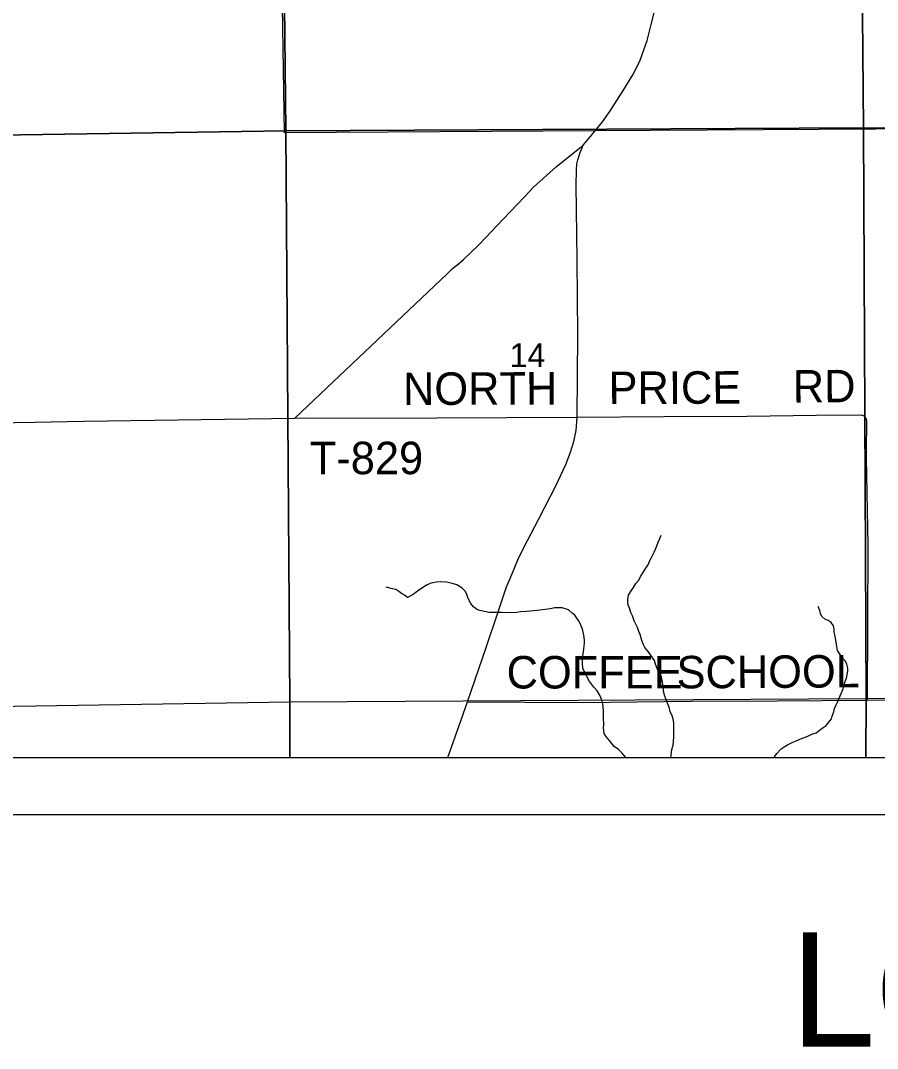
# Model space of a CAD drawing. Extents: x 0 to 34, y 0 to 22.
# Drawn here: x 3.079 to 4.579, y 13.591 to 15.389 of the extents above; entities that cross this region are included whole.
import ezdxf

# ---------------------------------------------------------------- set-up
doc = ezdxf.new("R2010")
doc.units = 0
for name, color, linetype in [('Default', 7, 'Continuous'), ('GM_X_Minor_River', 7, 'Continuous'), ('GM_X_Rail_Line', 7, 'Continuous'), ('GM_X_Section', 7, 'Continuous'), ('GM_X_Section_Text', 7, 'Continuous'), ('GM_X_State_Route', 7, 'Continuous'), ('GM_X_Township', 7, 'Continuous'), ('GM_X_Township_Road', 7, 'Continuous'), ('GM_X_Township_Road_Text', 7, 'Continuous'), ('SH_Cut_Line', 7, 'Continuous'), ('SH_Data', 7, 'Continuous'), ('SH_Text', 7, 'Continuous')]:
    doc.layers.add(name, color=color, linetype=linetype)

msp = doc.modelspace()

# ---------------------------------------------------------------- linework, layer by layer
at = {"layer": 'Default'}
for points in [[(2.5497, 14.1), (3.5508, 14.1), (3.5507, 14.1966), (2.5493, 14.1808)], [(3.5508, 14.1), (4.5592, 14.1), (4.5597, 14.2026), (3.5507, 14.1966)], [(4.5592, 14.1), (5.5573, 14.1), (5.5568, 14.2045), (4.5597, 14.2026)]]:
    msp.add_lwpolyline(points, close=True, dxfattribs=at)
at = {"layer": 'GM_X_Minor_River'}
for points in [[(4.2178, 14.1), (4.2187, 14.1084), (4.2197, 14.1141), (4.2215, 14.1213), (4.2221, 14.1278), (4.2227, 14.1358), (4.2232, 14.1472), (4.223, 14.1586), (4.2221, 14.165), (4.2192, 14.1745), (4.2168, 14.1797), (4.2148, 14.1881), (4.2116, 14.1952), (4.2096, 14.2009), (4.2064, 14.2091), (4.2051, 14.2163), (4.2041, 14.2247), (4.2032, 14.2315), (4.2015, 14.2402), (4.1995, 14.2451), (4.196, 14.2499), (4.1936, 14.2556), (4.1908, 14.2631), (4.1891, 14.2699), (4.1778, 14.2856), (4.1723, 14.2924), (4.17, 14.2973), (4.1671, 14.3048), (4.1643, 14.315), (4.1615, 14.3202), (4.1591, 14.3274), (4.1563, 14.3334), (4.1535, 14.3391), (4.1507, 14.3477), (4.1479, 14.3534), (4.1451, 14.3613), (4.1431, 14.3666), (4.1422, 14.3715), (4.1425, 14.3776), (4.1438, 14.3841), (4.1468, 14.3898), (4.1523, 14.3975), (4.1563, 14.4041), (4.1608, 14.4095), (4.1652, 14.4172), (4.1699, 14.4245), (4.174, 14.4314), (4.1788, 14.4384), (4.1805, 14.4437), (4.1835, 14.4487), (4.1864, 14.4545), (4.1886, 14.4594), (4.1915, 14.4656), (4.1954, 14.4767), (4.1983, 14.4828), (4.2005, 14.4889)], [(3.8583, 14.3902), (3.8517, 14.3969), (3.8432, 14.4021), (3.8371, 14.4035), (3.8302, 14.4056), (3.8249, 14.4066), (3.8146, 14.4072), (3.8074, 14.4066), (3.801, 14.4054), (3.7961, 14.4041), (3.7912, 14.4021), (3.7852, 14.3986), (3.774, 14.3911), (3.7665, 14.3849), (3.7567, 14.3801), (3.7517, 14.3842), (3.7463, 14.3871), (3.7413, 14.3904), (3.736, 14.3937), (3.7302, 14.3951), (3.7191, 14.3977)], [(4.1387, 14.1), (4.1322, 14.1081), (4.126, 14.114), (4.1187, 14.1192), (4.1097, 14.1304), (4.1039, 14.1371), (4.1007, 14.142), (4.1001, 14.1522), (4.1004, 14.1572), (4.1001, 14.1701), (4.0996, 14.1796), (4.0993, 14.1906), (4.0976, 14.1985), (4.094, 14.2079), (4.0885, 14.2165), (4.0827, 14.2229), (4.0741, 14.2349), (4.0713, 14.2413), (4.0666, 14.2506), (4.0638, 14.2555), (4.0632, 14.265), (4.063, 14.273), (4.0654, 14.2894), (4.066, 14.2951), (4.0667, 14.3), (4.0666, 14.305), (4.0656, 14.3141), (4.0631, 14.3246), (4.0591, 14.3341), (4.0563, 14.3397), (4.0497, 14.3487), (4.0447, 14.3524), (4.0385, 14.3583), (4.0274, 14.3615), (4.0202, 14.3617), (4.0145, 14.3616), (4.0066, 14.3603), (3.9979, 14.359), (3.9929, 14.3585), (3.9838, 14.3572), (3.9774, 14.3566), (3.9717, 14.3561), (3.9653, 14.3553), (3.9547, 14.3547), (3.9482, 14.3538), (3.927, 14.3533), (3.9217, 14.3536), (3.9141, 14.3538), (3.9061, 14.3536), (3.8996, 14.3539), (3.8836, 14.3573), (3.8783, 14.3591), (3.8725, 14.3636), (3.8674, 14.3692), (3.8647, 14.3748), (3.8623, 14.3801), (3.8607, 14.385), (3.8583, 14.3902)], [(4.3982, 14.1), (4.3992, 14.1011), (4.4032, 14.1069), (4.411, 14.1151), (4.4163, 14.1186), (4.4219, 14.1221), (4.4313, 14.1269), (4.4373, 14.1293), (4.4467, 14.1333), (4.4565, 14.1369), (4.4648, 14.1405), (4.4723, 14.1433), (4.4779, 14.1476), (4.4843, 14.1527), (4.4899, 14.1558), (4.4988, 14.1674), (4.5002, 14.1724), (4.503, 14.18), (4.5045, 14.1854), (4.5066, 14.1911), (4.5092, 14.1965), (4.5124, 14.2038), (4.5157, 14.2118), (4.5193, 14.2203), (4.521, 14.2268), (4.5228, 14.2329), (4.5253, 14.239), (4.5264, 14.2447), (4.5274, 14.2512), (4.5273, 14.2561), (4.5256, 14.2633), (4.5232, 14.2686), (4.5185, 14.2738), (4.513, 14.282), (4.5095, 14.2869), (4.5078, 14.2975), (4.5052, 14.3123), (4.5035, 14.3191), (4.5038, 14.3244), (4.5026, 14.3301), (4.4982, 14.3364), (4.4929, 14.3397), (4.4871, 14.3419), (4.4821, 14.3467), (4.4797, 14.352), (4.4784, 14.3573), (4.4756, 14.3641)]]:
    msp.add_lwpolyline(points, dxfattribs=at)
at = {"layer": 'GM_X_Rail_Line'}
msp.add_lwpolyline([(2.1, 17.2107), (2.1, 14.1), (5.5619, 14.1), (5.5608, 14.205), (5.5615, 14.2414), (5.5595, 14.6439), (5.5583, 14.9347), (5.5581, 14.9676), (5.5588, 15.1747), (5.5579, 15.2049), (4.0847, 15.1965), (3.5411, 15.1931), (3.5298, 15.9318), (3.5269, 16.3549), (3.511, 17.2267), (3.4711, 17.2262), (2.9494, 17.2203), (2.5218, 17.2155)], close=True, dxfattribs=at)
at = {"layer": 'GM_X_Section'}
for points in [[(4.5462, 16.1923), (5.5468, 16.2132), (5.5538, 15.2739), (5.5548, 15.2004), (4.5552, 15.2018)], [(2.5362, 16.1651), (3.5333, 16.1865), (3.5436, 15.1965), (2.5373, 15.181)], [(3.5333, 16.1865), (4.5462, 16.1923), (4.5552, 15.2018), (3.5436, 15.1965)], [(2.5373, 15.181), (3.5436, 15.1965), (3.5507, 14.1966), (2.5493, 14.1808)], [(3.5436, 15.1965), (4.5552, 15.2018), (4.5597, 14.2026), (3.5507, 14.1966)], [(4.5552, 15.2018), (5.5548, 15.2004), (5.5565, 14.239), (5.5568, 14.2045), (4.5597, 14.2026)]]:
    msp.add_lwpolyline(points, close=True, dxfattribs=at)
at = {"layer": 'GM_X_State_Route'}
for points in [[(4.1704, 15.3381), (4.1763, 15.3542), (4.183, 15.3824), (4.1962, 15.4339), (4.2116, 15.4924)], [(4.0644, 15.171), (4.0743, 15.1828), (4.0849, 15.1959), (4.0983, 15.212), (4.1109, 15.2303), (4.1354, 15.2687), (4.151, 15.2941), (4.1632, 15.3182), (4.1704, 15.3381)], [(3.8271, 14.1), (3.8507, 14.1656), (3.8615, 14.1974), (3.8942, 14.2921), (3.9162, 14.3568), (3.9302, 14.3983), (3.9362, 14.4132), (3.9432, 14.4302), (3.9498, 14.4457), (3.9605, 14.4672), (3.9858, 14.5161), (4.017, 14.5764), (4.0341, 14.6124), (4.042, 14.6342), (4.0477, 14.6528), (4.0518, 14.6721), (4.0537, 14.6952), (4.055, 14.8394), (4.0539, 14.9699), (4.0528, 15.0588), (4.0522, 15.1012), (4.0526, 15.1267), (4.0533, 15.1383), (4.0546, 15.1457), (4.0587, 15.1586), (4.0644, 15.171)]]:
    msp.add_lwpolyline(points, dxfattribs=at)
at = {"layer": 'GM_X_Township'}
msp.add_lwpolyline([(7.482, 15.8179), (7.4834, 15.2992), (7.3416, 15.297), (6.5709, 15.2859), (6.3575, 15.2833), (5.5569, 15.2761), (5.5579, 15.2049), (4.0847, 15.1965), (3.5411, 15.1931), (3.5298, 15.9318)], dxfattribs=at)
at = {"layer": 'GM_X_Township_Road'}
for points in [[(2.1, 14.6671), (2.19, 14.6684), (2.5484, 14.6774), (3.1035, 14.6866), (3.1904, 14.6884), (3.5595, 14.6939), (3.8262, 14.9464), (3.8356, 14.9553), (3.8461, 14.9638), (3.855, 14.9715), (3.8812, 14.9962), (3.8946, 15.0105), (3.9125, 15.0298), (3.9618, 15.0811), (3.9775, 15.0976), (4.0171, 15.1332), (4.0644, 15.171)], [(3.5595, 14.6939), (3.8073, 14.6941), (4.0537, 14.6952)], [(4.0537, 14.6952), (4.2063, 14.6964), (4.3513, 14.6969), (4.4723, 14.6986), (4.5517, 14.6993), (4.5556, 14.6975), (4.5585, 14.6945), (4.5601, 14.6893), (4.5605, 14.6825), (4.5603, 14.6682), (4.5598, 14.6561)], [(4.5598, 14.6561), (4.5596, 14.6511), (4.5596, 14.6236), (4.5623, 14.4709), (4.5616, 14.2005)], [(3.8615, 14.1974), (4.0624, 14.1963), (4.2539, 14.1985), (4.4042, 14.1993), (4.5616, 14.2005), (4.8315, 14.2014), (4.9063, 14.2005), (5.0007, 14.197), (5.2611, 14.1988), (5.561, 14.2045)]]:
    msp.add_lwpolyline(points, dxfattribs=at)
at = {"layer": 'SH_Cut_Line'}
msp.add_lwpolyline([(2.1, 17.2107), (2.1, 14.1), (8.9, 14.1)], dxfattribs=at)
at = {"layer": 'SH_Data'}
for p, q in [((2.1, 14.1), (8.9, 14.1)), ((2, 14), (9, 14))]:
    msp.add_line(p, q, dxfattribs=at)

# ---------------------------------------------------------------- texts
at = {"layer": 'GM_X_Section_Text'}
msp.add_text('14', height=0.04186, rotation=0, dxfattribs=at).set_placement((3.9356, 14.7829))
at = {"layer": 'GM_X_Township_Road_Text'}
for s, rotation, p in [('NORTH', 0.1983, (3.7489, 14.7166)), ('PRICE', 0.2328, (4.1088, 14.7182)), ('RD', 0.4946, (4.4315, 14.7207)), ('T-829', 0, (3.5856, 14.5956)), ('SCHOOL', 0.3439, (4.2279, 14.2207)), ('COFFEE', 0, (3.9302, 14.2207))]:
    msp.add_text(s, height=0.05682, rotation=rotation, dxfattribs=at).set_placement(p)
at = {"layer": 'SH_Text'}
msp.add_text('LOCATION MAP', height=0.2, dxfattribs=at).set_placement((4.4269, 13.5938))

doc.saveas('drawing.dxf')
